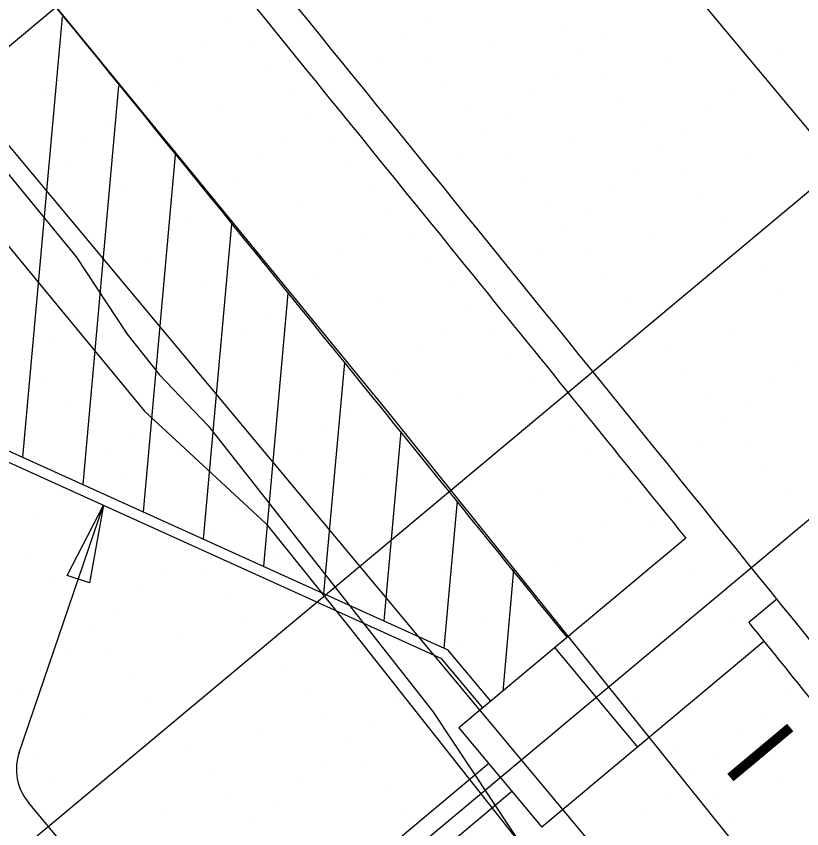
# Model space of a CAD drawing. Extents: x 2042995 to 2043795, y 305365 to 306249.
# Drawn here: x 2043404.15 to 2043429.34, y 305666.44 to 305692.47 of the extents above; entities that cross this region are included whole.
import ezdxf

# ---------------------------------------------------------------- set-up
doc = ezdxf.new("R2010")
doc.units = 0
for name, color, linetype in [('BR_AUTO DIMENSION', 7, 'Continuous'), ('BR_CENTER LINES', 7, 'Continuous'), ('BR_CONCRETE', 7, 'Continuous'), ('BR_EXIST_GROUND_CL', 7, 'Continuous'), ('BR_EXIST_GROUND_LT', 7, 'Continuous'), ('BR_EXIST_GROUND_RT', 7, 'Continuous'), ('BR_GRID DOTS', 7, 'Continuous'), ('BR_GRID LINES', 7, 'Continuous'), ('BR_PRESTRESSED BEAM', 7, 'Continuous'), ('BR_STRUCTURAL STEEL', 7, 'Continuous'), ('BR_TABLE LINES', 7, 'Continuous'), ('BR_TEXT', 7, 'Continuous')]:
    doc.layers.add(name, color=color, linetype=linetype)

msp = doc.modelspace()

# ---------------------------------------------------------------- linework, layer by layer
at = {"layer": 'BR_AUTO DIMENSION'}
for p, q in [((2043404.244, 305668.885), (2043406.951, 305676.801)), ((2043414.924, 305654.848), (2043404.542, 305667.278))]:
    msp.add_line(p, q, dxfattribs=at)
msp.add_lwpolyline([(2043405.787, 305674.556), (2043406.951, 305676.801), (2043406.497, 305674.314)], close=True, dxfattribs=at)
msp.add_arc((2043405.822, 305668.346), 1.667, 161.1254, 219.8684, dxfattribs=at)
at = {"layer": 'BR_CENTER LINES'}
msp.add_line((2043453.278, 305696.145), (2043389.013, 305642.47), dxfattribs=at)
at = {"layer": 'BR_CONCRETE'}
for p, q in [((2043374.419, 305691.891), (2043417.993, 305672.168)), ((2043374.472, 305691.501), (2043417.786, 305671.896)), ((2043425.623, 305675.744), (2043418.345, 305669.666)), ((2043428.532, 305673.791), (2043427.637, 305673.044)), ((2043428.125, 305672.44), (2043420.999, 305666.488)), ((2043419.369, 305670.521), (2043417.993, 305672.168)), ((2043421.415, 305672.23), (2043424.07, 305669.053)), ((2043419.113, 305670.307), (2043417.786, 305671.896)), ((2043418.345, 305669.666), (2043420.999, 305666.488))]:
    msp.add_line(p, q, dxfattribs=at)
for points in [[(2043139.109, 306017.548), (2043148.199, 306007.16), (2043160.233, 305993.368), (2043172.245, 305979.557), (2043184.234, 305965.727), (2043196.201, 305951.879), (2043208.145, 305938.012), (2043220.067, 305924.126), (2043231.966, 305910.221), (2043243.843, 305896.297), (2043255.698, 305882.355), (2043267.529, 305868.394), (2043279.339, 305854.414), (2043291.126, 305840.415), (2043302.89, 305826.398), (2043314.632, 305812.361), (2043326.352, 305798.306), (2043338.049, 305784.233), (2043349.724, 305770.14), (2043361.376, 305756.029), (2043373.005, 305741.899), (2043384.613, 305727.75), (2043396.197, 305713.582), (2043407.76, 305699.396), (2043419.299, 305685.191), (2043430.817, 305670.967), (2043442.311, 305656.724), (2043453.784, 305642.463), (2043465.234, 305628.182), (2043476.661, 305613.883), (2043488.066, 305599.566), (2043499.448, 305585.229), (2043510.808, 305570.874), (2043522.146, 305556.5), (2043533.461, 305542.107), (2043544.753, 305527.695), (2043547.219, 305524.543)], [(2043273.14, 305860.139), (2043278.86, 305853.362), (2043290.647, 305839.364), (2043302.411, 305825.346), (2043314.153, 305811.31), (2043325.873, 305797.255), (2043337.57, 305783.181), (2043349.245, 305769.089), (2043360.897, 305754.977), (2043372.526, 305740.847), (2043384.134, 305726.698), (2043395.718, 305712.531), (2043407.281, 305698.344), (2043418.82, 305684.139), (2043425.623, 305675.744)], [(2043427.637, 305673.044), (2043429.921, 305670.219), (2043440.203, 305657.481)]]:
    msp.add_spline(points, degree=3, dxfattribs=at)
at = {"layer": 'BR_EXIST_GROUND_CL'}
msp.add_lwpolyline([(2043338.156, 305736.064), (2043343.356, 305729.655), (2043359.035, 305710.311), (2043370.6, 305716.249), (2043373.991, 305717.972), (2043376.489, 305716.564), (2043384.158, 305712.004), (2043388.691, 305713.145), (2043388.719, 305713.157), (2043388.724, 305713.15), (2043388.86, 305712.984), (2043404.564, 305693.828), (2043404.746, 305693.605), (2043415.952, 305679.935), (2043416.228, 305679.59), (2043431.602, 305660.44), (2043431.917, 305660.046), (2043447.252, 305640.944), (2043447.607, 305640.502), (2043462.901, 305621.449), (2043463.289, 305620.965), (2043478.169, 305602.429), (2043493.131, 305583.244)], dxfattribs=at)
at = {"layer": 'BR_EXIST_GROUND_LT'}
msp.add_lwpolyline([(2043354.799, 305715.351), (2043359.926, 305717.738), (2043364.872, 305720.524), (2043365.854, 305721.02), (2043368.102, 305722.072), (2043368.313, 305722.175), (2043369.573, 305721.387), (2043370.345, 305720.837), (2043376.349, 305716.515), (2043382.505, 305710.7), (2043387.619, 305705.755), (2043390.235, 305701.607), (2043398.668, 305691.436), (2043408.268, 305679.814), (2043412.161, 305676.205), (2043414.832, 305672.889), (2043427.68, 305656.627), (2043430.646, 305652.948), (2043443.204, 305637.057), (2043446.485, 305632.99)], dxfattribs=at)
at = {"layer": 'BR_EXIST_GROUND_RT'}
msp.add_lwpolyline([(2043346.769, 305725.658), (2043363.272, 305705.271), (2043374.342, 305711.011), (2043376.064, 305711.93), (2043378.089, 305712.973), (2043379.626, 305712.231), (2043380.137, 305712.006), (2043383.072, 305710.363), (2043386.038, 305708.267), (2043387.272, 305707.367), (2043388.278, 305706.497), (2043390.439, 305703.811), (2043392.38, 305701.256), (2043399.25, 305693.074), (2043406.074, 305684.764), (2043407.71, 305682.279), (2043408.739, 305680.988), (2043410.315, 305679.334), (2043417.513, 305670.199), (2043422.514, 305662.658), (2043427.629, 305656.269), (2043439.785, 305641.081), (2043443.164, 305636.641), (2043455.044, 305621.797)], dxfattribs=at)
at = {"layer": 'BR_GRID DOTS'}
for p, q in [((2043417.458, 305692.382), (2043417.458, 305692.382)), ((2043411.056, 305692.247), (2043411.056, 305692.247)), ((2043406.063, 305691.986), (2043406.063, 305691.986)), ((2043413.874, 305691.994), (2043413.874, 305691.994)), ((2043421.684, 305692.003), (2043421.684, 305692.003)), ((2043423.092, 305691.876), (2043423.092, 305691.876)), ((2043410.289, 305691.606), (2043410.289, 305691.606)), ((2043416.691, 305691.741), (2043416.691, 305691.741)), ((2043411.697, 305691.48), (2043411.697, 305691.48)), ((2043419.508, 305691.488), (2043419.508, 305691.488)), ((2043428.726, 305691.371), (2043428.726, 305691.371)), ((2043406.704, 305691.218), (2043406.704, 305691.218)), ((2043415.923, 305691.1), (2043415.923, 305691.1)), ((2043422.325, 305691.235), (2043422.325, 305691.235)), ((2043409.521, 305690.965), (2043409.521, 305690.965)), ((2043417.332, 305690.974), (2043417.332, 305690.974)), ((2043425.142, 305690.982), (2043425.142, 305690.982)), ((2043412.338, 305690.712), (2043412.338, 305690.712)), ((2043421.557, 305690.594), (2043421.557, 305690.594)), ((2043427.959, 305690.729), (2043427.959, 305690.729)), ((2043407.345, 305690.451), (2043407.345, 305690.451)), ((2043408.754, 305690.324), (2043408.754, 305690.324)), ((2043415.156, 305690.459), (2043415.156, 305690.459)), ((2043422.966, 305690.468), (2043422.966, 305690.468)), ((2043417.973, 305690.206), (2043417.973, 305690.206)), ((2043427.191, 305690.088), (2043427.191, 305690.088)), ((2043405.169, 305689.936), (2043405.169, 305689.936)), ((2043412.98, 305689.945), (2043412.98, 305689.945)), ((2043414.388, 305689.818), (2043414.388, 305689.818)), ((2043420.79, 305689.953), (2043420.79, 305689.953)), ((2043407.986, 305689.683), (2043407.986, 305689.683)), ((2043423.607, 305689.7), (2043423.607, 305689.7)), ((2043410.803, 305689.43), (2043410.803, 305689.43)), ((2043418.614, 305689.439), (2043418.614, 305689.439)), ((2043420.022, 305689.312), (2043420.022, 305689.312)), ((2043426.424, 305689.447), (2043426.424, 305689.447)), ((2043407.219, 305689.042), (2043407.219, 305689.042)), ((2043413.621, 305689.177), (2043413.621, 305689.177)), ((2043408.627, 305688.916), (2043408.627, 305688.916)), ((2043416.438, 305688.924), (2043416.438, 305688.924)), ((2043424.248, 305688.933), (2043424.248, 305688.933)), ((2043425.656, 305688.806), (2043425.656, 305688.806)), ((2043412.853, 305688.536), (2043412.853, 305688.536)), ((2043419.255, 305688.671), (2043419.255, 305688.671)), ((2043406.451, 305688.401), (2043406.451, 305688.401)), ((2043414.262, 305688.41), (2043414.262, 305688.41)), ((2043422.072, 305688.418), (2043422.072, 305688.418)), ((2043409.268, 305688.148), (2043409.268, 305688.148)), ((2043418.487, 305688.03), (2043418.487, 305688.03)), ((2043424.889, 305688.165), (2043424.889, 305688.165)), ((2043405.684, 305687.76), (2043405.684, 305687.76)), ((2043412.086, 305687.895), (2043412.086, 305687.895)), ((2043419.896, 305687.904), (2043419.896, 305687.904)), ((2043427.706, 305687.912), (2043427.706, 305687.912)), ((2043414.903, 305687.642), (2043414.903, 305687.642)), ((2043424.121, 305687.524), (2043424.121, 305687.524)), ((2043409.909, 305687.381), (2043409.909, 305687.381)), ((2043411.318, 305687.254), (2043411.318, 305687.254)), ((2043417.72, 305687.389), (2043417.72, 305687.389)), ((2043425.53, 305687.398), (2043425.53, 305687.398)), ((2043404.916, 305687.119), (2043404.916, 305687.119)), ((2043420.537, 305687.136), (2043420.537, 305687.136)), ((2043407.733, 305686.866), (2043407.733, 305686.866)), ((2043415.544, 305686.875), (2043415.544, 305686.875)), ((2043416.952, 305686.748), (2043416.952, 305686.748)), ((2043423.354, 305686.883), (2043423.354, 305686.883)), ((2043410.55, 305686.613), (2043410.55, 305686.613)), ((2043426.171, 305686.63), (2043426.171, 305686.63)), ((2043413.368, 305686.36), (2043413.368, 305686.36)), ((2043421.178, 305686.369), (2043421.178, 305686.369)), ((2043422.586, 305686.242), (2043422.586, 305686.242)), ((2043409.783, 305685.972), (2043409.783, 305685.972)), ((2043416.185, 305686.107), (2043416.185, 305686.107)), ((2043411.191, 305685.846), (2043411.191, 305685.846)), ((2043419.002, 305685.854), (2043419.002, 305685.854)), ((2043426.812, 305685.863), (2043426.812, 305685.863)), ((2043415.417, 305685.466), (2043415.417, 305685.466)), ((2043421.819, 305685.601), (2043421.819, 305685.601)), ((2043409.015, 305685.331), (2043409.015, 305685.331)), ((2043416.826, 305685.34), (2043416.826, 305685.34)), ((2043424.636, 305685.348), (2043424.636, 305685.348)), ((2043411.833, 305685.078), (2043411.833, 305685.078)), ((2043421.051, 305684.96), (2043421.051, 305684.96)), ((2043422.46, 305684.834), (2043422.46, 305684.834)), ((2043408.248, 305684.69), (2043408.248, 305684.69)), ((2043414.65, 305684.825), (2043414.65, 305684.825)), ((2043417.467, 305684.572), (2043417.467, 305684.572)), ((2043412.474, 305684.311), (2043412.474, 305684.311)), ((2043420.284, 305684.319), (2043420.284, 305684.319)), ((2043428.094, 305684.328), (2043428.094, 305684.328)), ((2043404.663, 305684.302), (2043404.663, 305684.302)), ((2043407.48, 305684.049), (2043407.48, 305684.049)), ((2043413.882, 305684.184), (2043413.882, 305684.184)), ((2043423.101, 305684.066), (2043423.101, 305684.066)), ((2043410.297, 305683.796), (2043410.297, 305683.796)), ((2043418.108, 305683.805), (2043418.108, 305683.805)), ((2043413.115, 305683.543), (2043413.115, 305683.543)), ((2043419.516, 305683.678), (2043419.516, 305683.678)), ((2043428.735, 305683.56), (2043428.735, 305683.56)), ((2043406.713, 305683.408), (2043406.713, 305683.408)), ((2043415.932, 305683.29), (2043415.932, 305683.29)), ((2043423.742, 305683.299), (2043423.742, 305683.299)), ((2043418.749, 305683.037), (2043418.749, 305683.037)), ((2043405.945, 305682.767), (2043405.945, 305682.767)), ((2043412.347, 305682.902), (2043412.347, 305682.902)), ((2043413.756, 305682.776), (2043413.756, 305682.776)), ((2043421.566, 305682.784), (2043421.566, 305682.784)), ((2043411.58, 305682.261), (2043411.58, 305682.261)), ((2043417.981, 305682.396), (2043417.981, 305682.396)), ((2043419.39, 305682.27), (2043419.39, 305682.27)), ((2043427.2, 305682.278), (2043427.2, 305682.278)), ((2043405.178, 305682.126), (2043405.178, 305682.126)), ((2043414.397, 305682.008), (2043414.397, 305682.008)), ((2043417.214, 305681.755), (2043417.214, 305681.755)), ((2043425.024, 305681.764), (2043425.024, 305681.764)), ((2043404.41, 305681.485), (2043404.41, 305681.485)), ((2043410.812, 305681.62), (2043410.812, 305681.62)), ((2043420.031, 305681.502), (2043420.031, 305681.502)), ((2043407.227, 305681.232), (2043407.227, 305681.232)), ((2043415.038, 305681.241), (2043415.038, 305681.241)), ((2043429.25, 305681.384), (2043429.25, 305681.384)), ((2043410.044, 305680.979), (2043410.044, 305680.979)), ((2043416.446, 305681.114), (2043416.446, 305681.114)), ((2043425.665, 305680.996), (2043425.665, 305680.996)), ((2043405.051, 305680.718), (2043405.051, 305680.718)), ((2043412.862, 305680.726), (2043412.862, 305680.726)), ((2043420.672, 305680.735), (2043420.672, 305680.735)), ((2043428.482, 305680.743), (2043428.482, 305680.743)), ((2043415.679, 305680.473), (2043415.679, 305680.473)), ((2043409.277, 305680.338), (2043409.277, 305680.338)), ((2043418.496, 305680.22), (2043418.496, 305680.22)), ((2043426.306, 305680.229), (2043426.306, 305680.229)), ((2043405.692, 305679.95), (2043405.692, 305679.95)), ((2043427.715, 305680.102), (2043427.715, 305680.102)), ((2043408.509, 305679.697), (2043408.509, 305679.697)), ((2043414.911, 305679.832), (2043414.911, 305679.832)), ((2043416.32, 305679.706), (2043416.32, 305679.706)), ((2043424.13, 305679.714), (2043424.13, 305679.714)), ((2043426.947, 305679.461), (2043426.947, 305679.461)), ((2043406.333, 305679.182), (2043406.333, 305679.182)), ((2043414.144, 305679.191), (2043414.144, 305679.191)), ((2043421.954, 305679.2), (2043421.954, 305679.2)), ((2043407.742, 305679.056), (2043407.742, 305679.056)), ((2043416.961, 305678.938), (2043416.961, 305678.938)), ((2043404.157, 305678.668), (2043404.157, 305678.668)), ((2043426.18, 305678.82), (2043426.18, 305678.82)), ((2043427.588, 305678.694), (2043427.588, 305678.694)), ((2043406.974, 305678.415), (2043406.974, 305678.415)), ((2043413.376, 305678.55), (2043413.376, 305678.55)), ((2043422.595, 305678.432), (2043422.595, 305678.432)), ((2043409.792, 305678.162), (2043409.792, 305678.162)), ((2043417.602, 305678.171), (2043417.602, 305678.171)), ((2043425.412, 305678.179), (2043425.412, 305678.179)), ((2043412.609, 305677.909), (2043412.609, 305677.909)), ((2043428.229, 305677.926), (2043428.229, 305677.926)), ((2043406.207, 305677.774), (2043406.207, 305677.774)), ((2043407.615, 305677.647), (2043407.615, 305677.647)), ((2043415.426, 305677.656), (2043415.426, 305677.656)), ((2043423.236, 305677.665), (2043423.236, 305677.665)), ((2043424.644, 305677.538), (2043424.644, 305677.538)), ((2043405.439, 305677.133), (2043405.439, 305677.133)), ((2043411.841, 305677.268), (2043411.841, 305677.268)), ((2043421.06, 305677.15), (2043421.06, 305677.15)), ((2043428.87, 305677.159), (2043428.87, 305677.159)), ((2043408.256, 305676.88), (2043408.256, 305676.88)), ((2043423.877, 305676.897), (2043423.877, 305676.897)), ((2043411.074, 305676.627), (2043411.074, 305676.627)), ((2043418.884, 305676.635), (2043418.884, 305676.635)), ((2043426.694, 305676.644), (2043426.694, 305676.644)), ((2043404.672, 305676.492), (2043404.672, 305676.492)), ((2043423.109, 305676.256), (2043423.109, 305676.256)), ((2043408.897, 305676.112), (2043408.897, 305676.112)), ((2043410.306, 305675.986), (2043410.306, 305675.986)), ((2043424.518, 305676.13), (2043424.518, 305676.13)), ((2043419.525, 305675.868), (2043419.525, 305675.868)), ((2043428.744, 305675.75), (2043428.744, 305675.75)), ((2043406.721, 305675.598), (2043406.721, 305675.598)), ((2043422.342, 305675.615), (2043422.342, 305675.615)), ((2043409.539, 305675.345), (2043409.539, 305675.345)), ((2043425.159, 305675.362), (2043425.159, 305675.362)), ((2043404.545, 305675.083), (2043404.545, 305675.083)), ((2043412.356, 305675.092), (2043412.356, 305675.092)), ((2043420.166, 305675.1), (2043420.166, 305675.1)), ((2043421.574, 305674.974), (2043421.574, 305674.974)), ((2043427.976, 305675.109), (2043427.976, 305675.109)), ((2043408.771, 305674.704), (2043408.771, 305674.704)), ((2043410.18, 305674.577), (2043410.18, 305674.577)), ((2043417.99, 305674.586), (2043417.99, 305674.586)), ((2043425.8, 305674.594), (2043425.8, 305674.594)), ((2043427.209, 305674.468), (2043427.209, 305674.468)), ((2043405.186, 305674.316), (2043405.186, 305674.316)), ((2043420.807, 305674.333), (2043420.807, 305674.333)), ((2043408.003, 305674.063), (2043408.003, 305674.063)), ((2043423.624, 305674.08), (2043423.624, 305674.08)), ((2043410.821, 305673.81), (2043410.821, 305673.81)), ((2043420.039, 305673.692), (2043420.039, 305673.692)), ((2043426.441, 305673.827), (2043426.441, 305673.827)), ((2043405.827, 305673.548), (2043405.827, 305673.548)), ((2043407.236, 305673.422), (2043407.236, 305673.422)), ((2043421.448, 305673.565), (2043421.448, 305673.565)), ((2043429.258, 305673.574), (2043429.258, 305673.574)), ((2043425.674, 305673.186), (2043425.674, 305673.186)), ((2043411.462, 305673.042), (2043411.462, 305673.042)), ((2043419.272, 305673.051), (2043419.272, 305673.051)), ((2043427.082, 305673.059), (2043427.082, 305673.059)), ((2043406.468, 305672.781), (2043406.468, 305672.781)), ((2043422.089, 305672.798), (2043422.089, 305672.798)), ((2043409.286, 305672.528), (2043409.286, 305672.528)), ((2043418.504, 305672.41), (2043418.504, 305672.41)), ((2043424.906, 305672.545), (2043424.906, 305672.545)), ((2043405.701, 305672.14), (2043405.701, 305672.14)), ((2043427.723, 305672.292), (2043427.723, 305672.292)), ((2043407.109, 305672.013), (2043407.109, 305672.013)), ((2043414.92, 305672.022), (2043414.92, 305672.022)), ((2043422.73, 305672.03), (2043422.73, 305672.03)), ((2043424.139, 305671.904), (2043424.139, 305671.904)), ((2043417.737, 305671.769), (2043417.737, 305671.769)), ((2043404.933, 305671.499), (2043404.933, 305671.499)), ((2043412.744, 305671.507), (2043412.744, 305671.507)), ((2043420.554, 305671.516), (2043420.554, 305671.516)), ((2043428.364, 305671.524), (2043428.364, 305671.524)), ((2043407.75, 305671.246), (2043407.75, 305671.246)), ((2043416.969, 305671.128), (2043416.969, 305671.128)), ((2043423.371, 305671.263), (2043423.371, 305671.263)), ((2043404.166, 305670.858), (2043404.166, 305670.858)), ((2043426.188, 305671.01), (2043426.188, 305671.01)), ((2043413.385, 305670.74), (2043413.385, 305670.74)), ((2043422.603, 305670.622), (2043422.603, 305670.622)), ((2043429.005, 305670.757), (2043429.005, 305670.757)), ((2043408.392, 305670.478), (2043408.392, 305670.478)), ((2043416.202, 305670.487), (2043416.202, 305670.487)), ((2043424.012, 305670.495), (2043424.012, 305670.495)), ((2043428.238, 305670.116), (2043428.238, 305670.116)), ((2043406.215, 305669.964), (2043406.215, 305669.964)), ((2043414.026, 305669.972), (2043414.026, 305669.972)), ((2043415.434, 305669.846), (2043415.434, 305669.846)), ((2043421.836, 305669.981), (2043421.836, 305669.981)), ((2043424.653, 305669.728), (2043424.653, 305669.728)), ((2043427.47, 305669.475), (2043427.47, 305669.475)), ((2043411.85, 305669.458), (2043411.85, 305669.458)), ((2043421.068, 305669.34), (2043421.068, 305669.34)), ((2043414.667, 305669.205), (2043414.667, 305669.205)), ((2043417.484, 305668.952), (2043417.484, 305668.952)), ((2043425.294, 305668.96), (2043425.294, 305668.96)), ((2043409.674, 305668.943), (2043409.674, 305668.943)), ((2043420.301, 305668.699), (2043420.301, 305668.699)), ((2043426.703, 305668.834), (2043426.703, 305668.834)), ((2043404.68, 305668.682), (2043404.68, 305668.682)), ((2043413.899, 305668.564), (2043413.899, 305668.564)), ((2043415.308, 305668.437), (2043415.308, 305668.437)), ((2043423.118, 305668.446), (2043423.118, 305668.446)), ((2043410.315, 305668.176), (2043410.315, 305668.176)), ((2043425.935, 305668.193), (2043425.935, 305668.193)), ((2043405.321, 305667.914), (2043405.321, 305667.914)), ((2043413.132, 305667.923), (2043413.132, 305667.923)), ((2043419.533, 305668.058), (2043419.533, 305668.058)), ((2043428.752, 305667.94), (2043428.752, 305667.94)), ((2043415.949, 305667.67), (2043415.949, 305667.67)), ((2043410.956, 305667.408), (2043410.956, 305667.408)), ((2043418.766, 305667.417), (2043418.766, 305667.417)), ((2043425.168, 305667.552), (2043425.168, 305667.552)), ((2043426.576, 305667.425), (2043426.576, 305667.425)), ((2043412.364, 305667.282), (2043412.364, 305667.282)), ((2043408.78, 305666.894), (2043408.78, 305666.894)), ((2043416.59, 305666.902), (2043416.59, 305666.902)), ((2043424.4, 305666.911), (2043424.4, 305666.911)), ((2043411.597, 305666.641), (2043411.597, 305666.641)), ((2043417.998, 305666.776), (2043417.998, 305666.776)), ((2043427.217, 305666.658), (2043427.217, 305666.658))]:
    msp.add_line(p, q, dxfattribs=at)
at = {"layer": 'BR_GRID LINES'}
for p, q in [((2043137.788, 306038.16), (2043569.411, 305521.364)), ((2043122.438, 306025.339), (2043554.061, 305508.544)), ((2043463.754, 305741.471), (2043310.25, 305613.266)), ((2043476.574, 305726.121), (2043323.07, 305597.916))]:
    msp.add_line(p, q, dxfattribs=at)
at = {"layer": 'BR_PRESTRESSED BEAM'}
msp.add_spline([(2043269.336, 305856.962), (2043274.734, 305850.568), (2043286.521, 305836.569), (2043298.285, 305822.551), (2043310.027, 305808.515), (2043321.747, 305794.46), (2043333.444, 305780.386), (2043345.119, 305766.294), (2043356.771, 305752.183), (2043368.4, 305738.053), (2043380.007, 305723.904), (2043391.592, 305709.736), (2043403.154, 305695.55), (2043414.694, 305681.345), (2043421.811, 305672.561)], degree=3, dxfattribs=at)
at = {"layer": 'BR_STRUCTURAL STEEL'}
for p, q in [((2043419.298, 305668.525), (2043391.655, 305645.438)), ((2043420.046, 305667.63), (2043392.403, 305644.542))]:
    msp.add_line(p, q, dxfattribs=at)
at = {"layer": 'BR_TABLE LINES'}
for p, q in [((2043405.625, 305692.455), (2043404.357, 305678.34)), ((2043407.434, 305690.24), (2043406.287, 305677.467)), ((2043409.243, 305688.024), (2043408.217, 305676.593)), ((2043411.052, 305685.809), (2043410.146, 305675.72)), ((2043412.861, 305683.594), (2043412.076, 305674.847)), ((2043414.671, 305681.379), (2043414.006, 305673.973)), ((2043416.48, 305679.163), (2043415.935, 305673.1)), ((2043418.289, 305676.948), (2043417.865, 305672.226)), ((2043420.098, 305674.733), (2043419.748, 305670.838))]:
    msp.add_line(p, q, dxfattribs=at)

# ---------------------------------------------------------------- texts
at = {"layer": 'BR_TEXT'}
msp.add_text('I', height=2.5, rotation=309.8684, dxfattribs=at).set_placement((2043426.75, 305668.435))

doc.saveas('drawing.dxf')
